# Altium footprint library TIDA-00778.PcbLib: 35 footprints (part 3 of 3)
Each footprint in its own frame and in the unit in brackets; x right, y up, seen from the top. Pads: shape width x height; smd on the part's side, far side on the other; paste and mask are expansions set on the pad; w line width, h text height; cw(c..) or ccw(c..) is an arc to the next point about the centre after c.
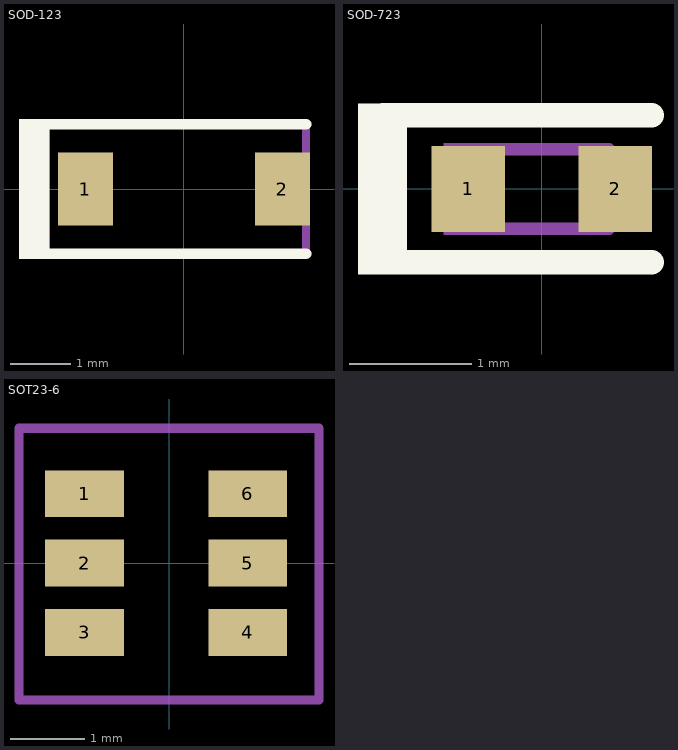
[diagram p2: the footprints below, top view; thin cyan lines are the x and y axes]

## SOD-123 [mm] "On Semi recommended land pattern"
height 1.35
pads (2):
  rect 0.915x1.22 smd: 1(-1.637,0) 2(1.637,0)
Top Overlay:
  rectangle: -2.743,-1.168 -2.235,1.168
  lines w0.178: -2.413,-1.079 2.032,-1.079 ; -2.413,1.079 2.032,1.079
Mechanical 5:
  rectangle: -2.743,-1.168 -2.235,1.168
  lines w0.127: -2.413,-1.079 2.032,-1.079 2.032,1.079 -2.413,1.079
  text ".Designator" at -1.956,-0.33 h0.76
3D body "SOD-123.stp": height 1.35, standoff 0, extent -1.932,-0.9 1.932,0.9

## SOD-723 [mm] "SMD, 2-Leads, Body 1x0.6mm"
height 0.65
pads (2):
  rect 0.6x0.7 smd: 1(-0.6,0) 2(0.6,0)
Top Overlay:
  rectangle: -1.5,-0.701 -1.1,0.699
  lines w0.2: -1.3,-0.6 0.9,-0.6 ; -1.3,0.6 0.9,0.6
Mechanical 5:
  rectangle: -0.801,-0.375 -0.551,0.375
  lines w0.1: -0.55,-0.325 0.55,-0.325 0.55,0.325 -0.55,0.325 -0.55,-0.325
  text ".Designator" at -1.143,0.37 h0.76
3D body: height 0.15, standoff 0, extent 0.55,-0.15 0.75,0.15
3D body: height 0.15, standoff 0, extent -0.75,-0.15 -0.55,0.15
3D body: height 0.65, standoff 0.65, extent -0.55,-0.325 -0.3,0.325
3D body: height 0.65, standoff 0.01, extent -0.55,-0.325 0.55,0.325

## SOT23-6 [mil]
pads (6):
  rect 42x25 smd: 1(-45,37) 2(-45,0) 3(-45,-37) 4(42,-37) 5(42,0) 6(42,37)
Mechanical 5:
  lines w5: -80,-73 -80,72 80,72 80,-73 -80,-73
  text ".Designator" at 31.5,8.55 h30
